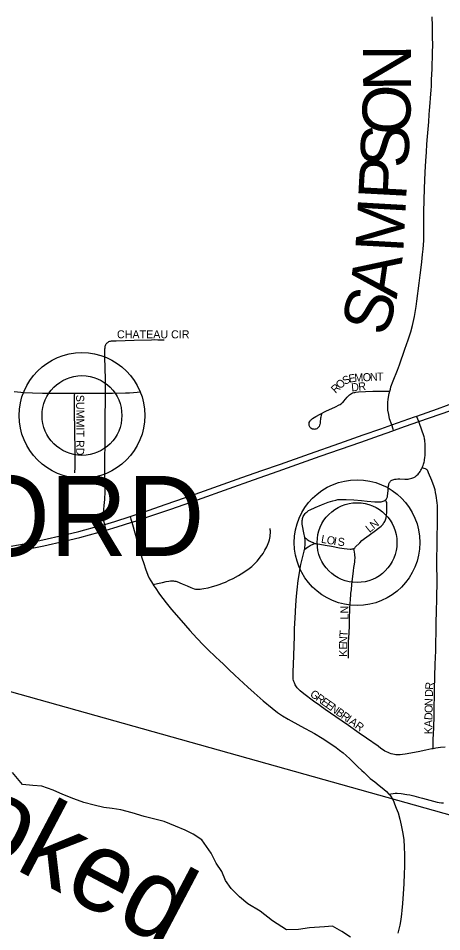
# Model space of a CAD drawing. Extents: x 0 to 34, y 0 to 22.
# Drawn here: x 29.474 to 29.975, y 17.062 to 18.143 of the extents above; entities that cross this region are included whole.
import ezdxf

# ---------------------------------------------------------------- set-up
doc = ezdxf.new("R2010")
doc.units = 0
for name, color, linetype in [('GM_X_Corporation_Text', 7, 'Continuous'), ('GM_X_County_Road', 7, 'Continuous'), ('GM_X_County_Road_Text', 7, 'Continuous'), ('GM_X_Minor_River', 7, 'Continuous'), ('GM_X_Minor_River_Text', 7, 'Continuous'), ('GM_X_Rail_Line', 7, 'Continuous'), ('GM_X_Township_Road', 7, 'Continuous'), ('GM_X_Township_Subdivision', 7, 'Continuous'), ('GM_X_Township_Subdivision_Text', 7, 'Continuous'), ('GM_X_Unincorporated', 7, 'Continuous'), ('GM_X_Unincorporated_Location', 7, 'Continuous'), ('GM_X_US_Route', 7, 'Continuous')]:
    doc.layers.add(name, color=color, linetype=linetype)

msp = doc.modelspace()

# ---------------------------------------------------------------- linework, layer by layer
at = {"layer": 'GM_X_County_Road'}
for points in [[(29.9135, 17.7018), (29.9141, 17.7043), (29.9148, 17.7069), (29.9175, 17.7141), (29.9225, 17.7268), (29.9248, 17.7331), (29.9313, 17.7515), (29.9351, 17.7624), (29.9382, 17.772), (29.9402, 17.7793), (29.9427, 17.7903), (29.9446, 17.8019), (29.9456, 17.8084), (29.9482, 17.8297), (29.9494, 17.8391), (29.9506, 17.8481), (29.9514, 17.8548), (29.9522, 17.8636), (29.9529, 17.8697), (29.9536, 17.8801), (29.9536, 17.8862), (29.9537, 17.8999), (29.9536, 17.9067), (29.9538, 17.9138), (29.9546, 17.9417), (29.9553, 17.9608), (29.956, 17.9743), (29.9568, 17.9846), (29.9575, 17.9941), (29.9581, 18.003), (29.9589, 18.0119), (29.9595, 18.0203), (29.9602, 18.0291), (29.9605, 18.0337), (29.9614, 18.043), (29.9618, 18.0483), (29.9622, 18.0535), (29.9625, 18.0579), (29.9627, 18.0627), (29.963, 18.0706), (29.9636, 18.0826), (29.9642, 18.1024), (29.9643, 18.1115), (29.9642, 18.1205), (29.9639, 18.1378), (29.9638, 18.1407), (29.9636, 18.1446)], [(29.9157, 17.6619), (29.9133, 17.6692), (29.9122, 17.674), (29.9113, 17.6794), (29.911, 17.6839), (29.911, 17.6864), (29.9112, 17.6887), (29.9115, 17.6919), (29.912, 17.6947), (29.9128, 17.699), (29.9135, 17.7018)], [(29.918, 17.6552), (29.9174, 17.6569), (29.9157, 17.6619)], [(29.606, 17.5535), (29.6069, 17.5505), (29.608, 17.5466)], [(29.608, 17.5466), (29.6125, 17.5314), (29.6149, 17.5224), (29.6201, 17.5045), (29.6222, 17.498), (29.6243, 17.4915), (29.6272, 17.4839), (29.6287, 17.4807), (29.6305, 17.4772), (29.6333, 17.4729)], [(29.6333, 17.4729), (29.6338, 17.4719), (29.6356, 17.4693), (29.641, 17.4617), (29.6488, 17.4513), (29.6552, 17.4436), (29.6665, 17.4303), (29.6767, 17.4187), (29.6851, 17.4094), (29.6928, 17.4013), (29.6982, 17.3961), (29.7072, 17.3876), (29.7122, 17.3829), (29.7162, 17.3791), (29.7229, 17.3726), (29.7301, 17.3658), (29.7456, 17.3515), (29.753, 17.3448), (29.7637, 17.3355), (29.7742, 17.3267), (29.7807, 17.3217), (29.7864, 17.3178), (29.7933, 17.3136), (29.808, 17.3056), (29.8243, 17.2966), (29.8333, 17.2911), (29.8447, 17.2836), (29.8498, 17.2801), (29.8538, 17.2772), (29.8582, 17.2738), (29.862, 17.2706), (29.8661, 17.2669), (29.8709, 17.2621), (29.8753, 17.2577), (29.8802, 17.253), (29.883, 17.2505), (29.8867, 17.2471), (29.8904, 17.2437), (29.8956, 17.2394), (29.901, 17.2352), (29.9063, 17.2309), (29.9096, 17.2281), (29.9125, 17.225), (29.9127, 17.2249)], [(29.9127, 17.2249), (29.9141, 17.2232), (29.9158, 17.2208), (29.9178, 17.217), (29.9192, 17.2137), (29.9211, 17.2085), (29.9232, 17.2027), (29.9252, 17.1955), (29.927, 17.1884), (29.9286, 17.1805), (29.9301, 17.1714), (29.9306, 17.1621), (29.931, 17.1535), (29.931, 17.1448), (29.9309, 17.1392), (29.9306, 17.1312), (29.9299, 17.1188), (29.9292, 17.107), (29.9284, 17.0958), (29.9276, 17.0872), (29.9273, 17.0835), (29.9265, 17.0767), (29.9253, 17.07), (29.9242, 17.0653), (29.9228, 17.0606)]]:
    msp.add_lwpolyline(points, dxfattribs=at)
at = {"layer": 'GM_X_Minor_River'}
msp.add_lwpolyline([(29.867, 17.0557), (29.8567, 17.0625), (29.8457, 17.0688), (29.8362, 17.068), (29.8184, 17.0667), (29.8052, 17.0648), (29.7911, 17.0643), (29.7748, 17.0752), (29.7599, 17.0865), (29.7454, 17.0951), (29.7355, 17.1034), (29.7256, 17.1132), (29.7191, 17.123), (29.7145, 17.1336), (29.708, 17.1434), (29.7022, 17.1551), (29.6911, 17.171), (29.6808, 17.1778), (29.6713, 17.1823), (29.6599, 17.1871), (29.6462, 17.1927), (29.6337, 17.1957), (29.6227, 17.1986), (29.6086, 17.2027), (29.5949, 17.2064), (29.5847, 17.2079), (29.5748, 17.2093), (29.5634, 17.2119), (29.5513, 17.2152), (29.5395, 17.2193), (29.5266, 17.2246), (29.5151, 17.2298), (29.5015, 17.2346), (29.4908, 17.2353), (29.4787, 17.2364), (29.4669, 17.2507)], dxfattribs=at)
at = {"layer": 'GM_X_Rail_Line'}
msp.add_lwpolyline([(29.3726, 17.3721), (29.8127, 17.2488), (30.4007, 17.0836), (30.5165, 17.0512), (30.5557, 17.04), (30.5898, 17.0311), (30.6117, 17.0259), (30.6508, 17.019), (30.6708, 17.0167), (30.6976, 17.015), (30.7226, 17.0145), (30.7453, 17.015), (30.7692, 17.0164), (30.7894, 17.0185), (30.8154, 17.0221), (30.8167, 17.0224)], dxfattribs=at)
at = {"layer": 'GM_X_Township_Road'}
for points in [[(29.6333, 17.4729), (29.6383, 17.4741), (29.6445, 17.4755), (29.6488, 17.4765), (29.6517, 17.477), (29.6539, 17.4773), (29.6557, 17.4774), (29.6565, 17.4774), (29.6575, 17.4773), (29.6587, 17.4771), (29.6602, 17.4768), (29.6614, 17.4764), (29.6676, 17.4739), (29.6735, 17.4713), (29.6779, 17.4694), (29.6818, 17.468), (29.6835, 17.4677), (29.6851, 17.4675), (29.6868, 17.4674), (29.689, 17.4676), (29.6909, 17.4678), (29.6935, 17.4682), (29.6983, 17.4692), (29.7034, 17.4705), (29.7078, 17.4718), (29.7126, 17.4735), (29.7156, 17.4746), (29.719, 17.476), (29.7235, 17.478), (29.7279, 17.4803), (29.7344, 17.4838), (29.7407, 17.4876), (29.7468, 17.4918), (29.7502, 17.4945), (29.7534, 17.4974), (29.7564, 17.5005), (29.7582, 17.5027), (29.7602, 17.5053), (29.7634, 17.5098), (29.7655, 17.5135), (29.7678, 17.5178), (29.7695, 17.5216), (29.7703, 17.5236), (29.7709, 17.5257), (29.7713, 17.5277), (29.7717, 17.5298), (29.772, 17.5318), (29.7722, 17.5336), (29.7723, 17.5348), (29.7722, 17.5358), (29.7722, 17.5367), (29.772, 17.5378), (29.7717, 17.5392)], [(29.9127, 17.2249), (29.9148, 17.2253), (29.9175, 17.2259), (29.9197, 17.2262), (29.9221, 17.2261), (29.927, 17.2257), (29.9336, 17.2247), (29.9373, 17.2241), (29.9421, 17.223), (29.9475, 17.2216), (29.9522, 17.2203), (29.9695, 17.2155), (29.9719, 17.2151), (29.9746, 17.2148), (29.9771, 17.2146)]]:
    msp.add_lwpolyline(points, dxfattribs=at)
at = {"layer": 'GM_X_Township_Subdivision'}
for points in [[(29.5769, 17.6994), (29.5769, 17.71), (29.5768, 17.7189), (29.5767, 17.7264), (29.5765, 17.7321), (29.5763, 17.7389), (29.5763, 17.7482), (29.5763, 17.752), (29.5764, 17.7531), (29.5764, 17.754), (29.5766, 17.7551), (29.5769, 17.756), (29.5773, 17.7569), (29.5777, 17.7576), (29.5782, 17.7583), (29.5789, 17.759), (29.5795, 17.7595), (29.5803, 17.76), (29.5809, 17.7604)], [(29.5809, 17.7604), (29.582, 17.7609), (29.5828, 17.7611), (29.5839, 17.7612), (29.5854, 17.7613), (29.5895, 17.7615), (29.6107, 17.762), (29.6314, 17.7627), (29.635, 17.7628), (29.639, 17.7627), (29.6465, 17.7624)], [(29.4687, 17.7012), (29.4805, 17.7003), (29.4904, 17.6997), (29.5022, 17.6994), (29.5185, 17.6993), (29.5328, 17.6993), (29.5406, 17.6994)], [(29.5408, 17.6051), (29.541, 17.612), (29.5411, 17.6166), (29.5411, 17.6227), (29.541, 17.6316), (29.541, 17.6387), (29.5408, 17.6474), (29.5406, 17.6567), (29.5405, 17.6629), (29.5404, 17.6702), (29.5402, 17.6802), (29.5402, 17.6877), (29.5404, 17.6968), (29.5406, 17.6994)], [(29.5406, 17.6994), (29.5603, 17.6995), (29.5728, 17.6994), (29.5769, 17.6994)], [(29.576, 17.5442), (29.575, 17.5478), (29.5747, 17.5502), (29.5745, 17.5527), (29.5745, 17.5552), (29.5746, 17.5576), (29.5749, 17.5618), (29.5754, 17.5665), (29.5758, 17.5702), (29.5761, 17.5738), (29.5763, 17.5766), (29.5765, 17.5798), (29.5764, 17.5901), (29.5763, 17.6039), (29.5763, 17.6119), (29.5763, 17.6207), (29.5765, 17.6404), (29.5766, 17.6526), (29.5767, 17.6769), (29.5769, 17.6862), (29.5769, 17.6955), (29.5769, 17.6994)], [(29.5769, 17.6994), (29.5853, 17.6995), (29.6007, 17.6997), (29.6055, 17.6999), (29.61, 17.7002), (29.6145, 17.7006), (29.6186, 17.7011)], [(29.833, 17.6752), (29.8328, 17.6747), (29.8323, 17.6734), (29.8318, 17.671), (29.8316, 17.6698), (29.8313, 17.6686), (29.8311, 17.6662), (29.8309, 17.6638), (29.8305, 17.6624), (29.8302, 17.6614), (29.8297, 17.6601), (29.8287, 17.6588), (29.8277, 17.6579), (29.827, 17.6574), (29.826, 17.657), (29.8254, 17.6568), (29.825, 17.6567), (29.824, 17.6566), (29.8238, 17.6567), (29.8229, 17.6567), (29.8219, 17.657), (29.8212, 17.6573), (29.8201, 17.6579), (29.8192, 17.6588), (29.8188, 17.6594), (29.8184, 17.6602), (29.8181, 17.6612), (29.8179, 17.6626), (29.818, 17.6639), (29.8182, 17.6649), (29.8188, 17.6659), (29.8191, 17.6665), (29.8197, 17.6673), (29.8204, 17.668), (29.822, 17.6693), (29.8239, 17.6706), (29.826, 17.6718), (29.831, 17.6747), (29.8379, 17.6782), (29.8493, 17.6834), (29.8537, 17.6856), (29.8547, 17.6862), (29.8565, 17.6874), (29.8575, 17.6882), (29.8583, 17.6889), (29.8592, 17.69), (29.8629, 17.6946), (29.8644, 17.6962), (29.8658, 17.6975), (29.8669, 17.6983), (29.8682, 17.699), (29.8695, 17.6997), (29.8708, 17.7001), (29.872, 17.7004), (29.8733, 17.7007), (29.8766, 17.7009), (29.8846, 17.7012), (29.8933, 17.7016), (29.896, 17.7017), (29.9135, 17.7018)], [(29.9477, 17.6657), (29.9456, 17.6716), (29.9453, 17.6723)], [(29.9517, 17.6111), (29.9522, 17.6121), (29.9528, 17.6137), (29.9535, 17.6156), (29.9538, 17.6167), (29.9541, 17.6178), (29.9545, 17.6193), (29.9547, 17.6209), (29.955, 17.6229), (29.9553, 17.6261), (29.9554, 17.6294), (29.9554, 17.6367), (29.9552, 17.6396), (29.955, 17.6425), (29.9548, 17.6437), (29.9547, 17.6449), (29.9545, 17.646), (29.9542, 17.6476), (29.9539, 17.6488), (29.9534, 17.6503), (29.9519, 17.6544), (29.9477, 17.6657)], [(29.9085, 17.573), (29.9085, 17.5731), (29.9092, 17.5737), (29.9097, 17.5744), (29.9101, 17.5752), (29.9105, 17.5761), (29.9107, 17.5769), (29.9109, 17.5779), (29.9114, 17.584), (29.9117, 17.5871), (29.9119, 17.5896), (29.9122, 17.5911), (29.9125, 17.5923), (29.9128, 17.5931), (29.9133, 17.5939), (29.9138, 17.5946), (29.9144, 17.5952), (29.9151, 17.5959), (29.9159, 17.5964), (29.917, 17.5969), (29.9183, 17.5973), (29.9194, 17.5976), (29.9209, 17.5978), (29.9228, 17.5979), (29.9252, 17.5979), (29.9314, 17.5977), (29.9334, 17.5978), (29.9351, 17.5978), (29.9365, 17.598), (29.9379, 17.5983), (29.9395, 17.5987), (29.9409, 17.5993), (29.9421, 17.5998), (29.9433, 17.6005), (29.9442, 17.6012), (29.9452, 17.602), (29.947, 17.6037), (29.9477, 17.6046), (29.9486, 17.6056), (29.9495, 17.6069), (29.9503, 17.6083), (29.951, 17.6096), (29.9517, 17.6111)], [(29.9689, 17.4429), (29.969, 17.4543), (29.9694, 17.4799), (29.9693, 17.4953), (29.9697, 17.5276), (29.9701, 17.5462), (29.97, 17.5626), (29.9698, 17.5666), (29.9695, 17.5697), (29.9693, 17.5723), (29.9689, 17.5756), (29.9685, 17.5783), (29.9677, 17.5817), (29.967, 17.5849), (29.9659, 17.5884), (29.9632, 17.5961), (29.9594, 17.6053), (29.9585, 17.6075), (29.958, 17.6083), (29.9574, 17.6089), (29.9567, 17.6095), (29.9556, 17.6099), (29.9542, 17.6103), (29.9517, 17.6111)], [(29.8127, 17.5287), (29.8116, 17.5342), (29.8101, 17.5424), (29.8098, 17.5444), (29.8097, 17.5459), (29.8097, 17.5474), (29.8098, 17.5487), (29.81, 17.55), (29.8103, 17.5512), (29.8107, 17.5524), (29.8111, 17.5536), (29.8117, 17.5548), (29.8124, 17.5559), (29.8134, 17.5571), (29.8144, 17.5582), (29.8155, 17.5592), (29.8171, 17.5604), (29.8193, 17.5615), (29.8252, 17.5643), (29.8328, 17.5674), (29.8406, 17.5703), (29.8461, 17.5721), (29.8494, 17.573), (29.852, 17.5735), (29.8547, 17.5737), (29.8578, 17.5738), (29.8619, 17.5737), (29.8708, 17.5732), (29.8799, 17.5724), (29.8865, 17.5718), (29.8958, 17.571), (29.9008, 17.5709), (29.9031, 17.571), (29.9045, 17.5712), (29.9057, 17.5715), (29.9068, 17.5719), (29.9077, 17.5724), (29.9085, 17.573)], [(29.8709, 17.5158), (29.8719, 17.5165), (29.8726, 17.5172), (29.8778, 17.5225), (29.8805, 17.525), (29.8835, 17.5273), (29.8889, 17.5314), (29.8964, 17.537), (29.8999, 17.5395), (29.9033, 17.5422), (29.9045, 17.5433), (29.9056, 17.5446), (29.9062, 17.5455), (29.9068, 17.5463), (29.9074, 17.5474), (29.9079, 17.5483), (29.9083, 17.5494), (29.9088, 17.5507), (29.9091, 17.5519), (29.9096, 17.555), (29.9098, 17.5584), (29.9101, 17.5675), (29.91, 17.5688), (29.9098, 17.5699), (29.9093, 17.5713), (29.9085, 17.573)], [(29.5777, 17.5374), (29.5775, 17.5384), (29.576, 17.5442)], [(29.8126, 17.5145), (29.8127, 17.5151), (29.813, 17.5173), (29.8133, 17.5196), (29.8134, 17.5219), (29.8134, 17.524), (29.8132, 17.526), (29.8127, 17.5287)], [(29.8126, 17.5145), (29.8145, 17.5161), (29.8159, 17.5171), (29.817, 17.5178), (29.818, 17.5185), (29.8193, 17.5192), (29.8207, 17.5199), (29.8219, 17.5205), (29.8235, 17.521), (29.826, 17.5217)], [(29.8127, 17.5287), (29.8137, 17.5279), (29.8144, 17.5273), (29.8151, 17.5268), (29.8158, 17.5263), (29.817, 17.5255), (29.8182, 17.5246), (29.8194, 17.524), (29.8204, 17.5235), (29.8214, 17.523), (29.8226, 17.5226), (29.8241, 17.5221), (29.8259, 17.5217), (29.826, 17.5217)], [(29.826, 17.5217), (29.8305, 17.5209), (29.8371, 17.5195), (29.8444, 17.5182), (29.8539, 17.5165), (29.8595, 17.5157), (29.8665, 17.515), (29.8678, 17.515), (29.869, 17.5151), (29.8696, 17.5152), (29.8703, 17.5154), (29.8709, 17.5158)], [(29.8305, 17.3298), (29.8231, 17.3352), (29.8116, 17.3437), (29.8072, 17.3473), (29.8057, 17.3488), (29.8046, 17.3499), (29.8038, 17.3509), (29.8031, 17.3518), (29.8022, 17.3532), (29.8016, 17.3544), (29.801, 17.3556), (29.8005, 17.3567), (29.8, 17.3581), (29.7996, 17.3596), (29.7992, 17.3611), (29.799, 17.3627), (29.7989, 17.3648), (29.7989, 17.3673), (29.799, 17.3697), (29.7999, 17.3882), (29.8001, 17.4012), (29.8005, 17.411), (29.8008, 17.421), (29.8014, 17.4333), (29.8024, 17.4486), (29.8032, 17.4591), (29.8038, 17.4668), (29.8051, 17.4778), (29.8064, 17.4867), (29.8073, 17.4924), (29.8081, 17.4966), (29.8093, 17.5015), (29.8114, 17.5095), (29.8121, 17.5125), (29.8126, 17.5145)], [(29.8644, 17.3857), (29.8644, 17.3894), (29.8645, 17.3974), (29.8647, 17.4054), (29.8652, 17.4154), (29.8656, 17.4245), (29.8659, 17.4334), (29.8663, 17.4439), (29.8666, 17.4517), (29.8668, 17.4543), (29.8671, 17.4569), (29.8673, 17.4596), (29.8675, 17.4626), (29.868, 17.4669), (29.8687, 17.4733), (29.87, 17.4856), (29.8705, 17.4894), (29.871, 17.4933), (29.8716, 17.497), (29.872, 17.5), (29.8722, 17.5021), (29.8723, 17.504), (29.8723, 17.5053), (29.8721, 17.5075), (29.872, 17.5093), (29.8718, 17.5108), (29.8712, 17.5139), (29.8709, 17.5158)], [(29.965, 17.2788), (29.965, 17.281), (29.965, 17.2844), (29.965, 17.2905), (29.9651, 17.2954), (29.9654, 17.3045), (29.9658, 17.3169), (29.9661, 17.3297), (29.9664, 17.3394), (29.9665, 17.3494), (29.9673, 17.3787), (29.9678, 17.3946), (29.9685, 17.4262), (29.9689, 17.4429)], [(29.965, 17.2788), (29.9632, 17.2786), (29.956, 17.277), (29.9469, 17.2749), (29.9316, 17.2723), (29.9285, 17.2719), (29.9256, 17.2715), (29.924, 17.2715), (29.9224, 17.2715), (29.9206, 17.2717), (29.9189, 17.272), (29.9169, 17.2724), (29.9151, 17.2728), (29.9133, 17.2735), (29.9115, 17.2741), (29.9095, 17.2751), (29.9077, 17.276), (29.9061, 17.277), (29.9028, 17.2792), (29.8995, 17.2816), (29.8858, 17.2912), (29.8772, 17.2972), (29.8644, 17.3061), (29.8496, 17.3164), (29.837, 17.325), (29.831, 17.3293), (29.8305, 17.3298)], [(29.979, 17.2805), (29.9736, 17.28), (29.968, 17.2793), (29.965, 17.2788)]]:
    msp.add_lwpolyline(points, dxfattribs=at)
at = {"layer": 'GM_X_Unincorporated'}
for centre, radius in [((29.5491, 17.673), 0.0744), ((29.5491, 17.673), 0.0472), ((29.8747, 17.5226), 0.0744), ((29.8747, 17.5226), 0.0472)]:
    msp.add_circle(centre, radius, dxfattribs=at)
at = {"layer": 'GM_X_Unincorporated_Location'}
for p, q in [((29.5491, 17.673), (29.5491, 17.673)), ((29.8747, 17.5226), (29.8747, 17.5226))]:
    msp.add_line(p, q, dxfattribs=at)
at = {"layer": 'GM_X_US_Route'}
for points in [[(29.4553, 17.5096), (29.4798, 17.5139), (29.5041, 17.5188), (29.5279, 17.5242), (29.5466, 17.5288), (29.5694, 17.535), (29.5777, 17.5374), (29.5906, 17.5411), (29.608, 17.5466), (29.6126, 17.548), (29.6295, 17.5537), (29.6541, 17.5623), (29.6857, 17.5734), (29.7232, 17.5866), (29.752, 17.5969), (29.7813, 17.6071), (29.8312, 17.6247), (29.8791, 17.6415), (29.9012, 17.6492), (29.9171, 17.6549), (29.918, 17.6552), (29.9322, 17.6602), (29.9477, 17.6657), (29.9982, 17.6834)], [(29.458, 17.5173), (29.4805, 17.5212), (29.4993, 17.525), (29.5302, 17.5321), (29.5453, 17.5358), (29.5711, 17.5429), (29.576, 17.5442), (29.5879, 17.5477), (29.606, 17.5535), (29.6098, 17.5547), (29.6288, 17.561), (29.6476, 17.5676), (29.683, 17.5798), (29.7383, 17.5995), (29.762, 17.6078), (29.784, 17.6156), (29.8184, 17.6277), (29.8543, 17.6404), (29.8821, 17.6501), (29.9029, 17.6574), (29.9157, 17.6619), (29.9426, 17.6713), (29.9453, 17.6723), (29.9698, 17.6809), (29.9914, 17.6886)]]:
    msp.add_lwpolyline(points, dxfattribs=at)

# ---------------------------------------------------------------- texts
at = {"layer": 'GM_X_Corporation_Text'}
msp.add_text('NEW CONCORD', height=0.094697, rotation=0, dxfattribs=at).set_placement((28.7092, 17.5068))
at = {"layer": 'GM_X_County_Road_Text'}
for s, rotation, p in [('N', 90.3473, (29.9388, 18.057)), ('O', 87.8176, (29.9369, 18.0043)), ('S', 86.9454, (29.9348, 17.9651)), ('P', 86.9412, (29.9327, 17.9268)), ('M', 86.8032, (29.9293, 17.8651)), ('A', 81.8151, (29.9216, 17.8102)), ('S', 73.7759, (29.9091, 17.7649))]:
    msp.add_text(s, height=0.0568, rotation=rotation, dxfattribs=at).set_placement(p)
at = {"layer": 'GM_X_Minor_River_Text'}
msp.add_text('Crooked', height=0.09469, rotation=332.1843, dxfattribs=at).set_placement((29.2254, 17.2651))
at = {"layer": 'GM_X_Township_Subdivision_Text'}
for s, rotation, p in [('CHATEAU CIR', 0, (29.5905, 17.7643)), ('O', 42.977, (29.8547, 17.7037)), ('S', 27.2369, (29.8603, 17.709)), ('E', 8.6672, (29.8654, 17.7118)), ('M', 3.2617, (29.8718, 17.7128)), ('O', 3.0829, (29.8817, 17.7134)), ('N', 3.1057, (29.8901, 17.7138)), ('T', 0.3279, (29.8983, 17.7143)), ('R', 42.973, (29.8492, 17.6986)), ('D', 4.858, (29.8682, 17.7015)), ('R', 5.6921, (29.8766, 17.7023)), ('SUMMIT RD', 270, (29.5422, 17.6975)), ('L', 38.8262, (29.8894, 17.5339)), ('N', 38.9471, (29.8946, 17.5381)), ('L', 349.9493, (29.8316, 17.5226)), ('O', 349.9376, (29.8382, 17.5215)), ('I', 349.9414, (29.8464, 17.52)), ('S', 354.8459, (29.8514, 17.5192)), ('LN', 90, (29.8645, 17.4317)), ('N', 87.836, (29.8629, 17.4024)), ('T', 86.6929, (29.8632, 17.4107)), ('E', 89.8087, (29.8629, 17.3959)), ('K', 89.9563, (29.8629, 17.3875)), ('R', 84.9661, (29.9646, 17.3482)), ('G', 324.752, (29.8182, 17.3415)), ('D', 88.6012, (29.9644, 17.34)), ('R', 324.7579, (29.825, 17.3367)), ('E', 324.7259, (29.8311, 17.3323)), ('E', 324.7765, (29.8366, 17.3285)), ('N', 89.0819, (29.9642, 17.3292)), ('N', 324.752, (29.842, 17.3246)), ('B', 324.7579, (29.8488, 17.3198)), ('O', 89.0819, (29.9641, 17.3209)), ('R', 324.7474, (29.8549, 17.3155)), ('I', 324.7215, (29.8611, 17.3112)), ('A', 324.773, (29.8645, 17.3088)), ('D', 89.0819, (29.9639, 17.3126)), ('R', 324.943, (29.8713, 17.3039)), ('K', 89.0819, (29.9637, 17.2959)), ('A', 89.0819, (29.9638, 17.3042))]:
    msp.add_text(s, height=0.00947, rotation=rotation, dxfattribs=at).set_placement(p)

doc.saveas('drawing.dxf')
